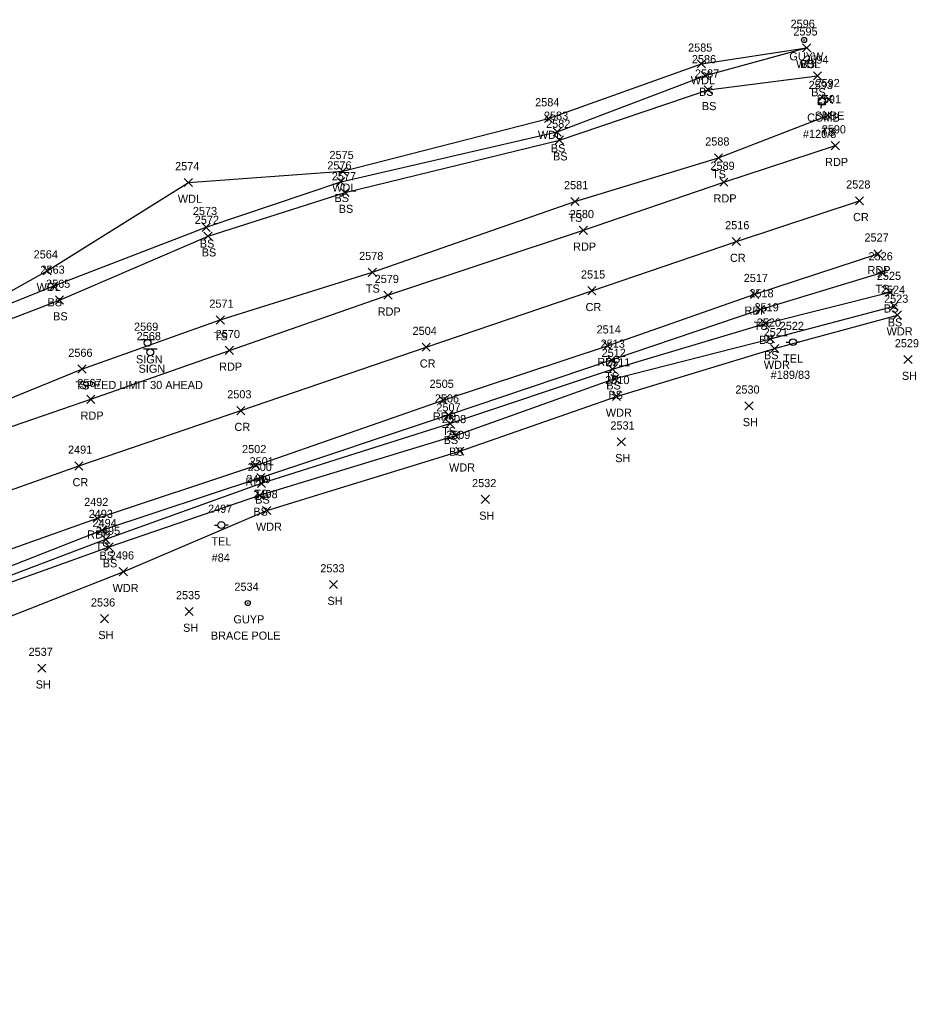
# Model space of a CAD drawing. Extents: x 1699408 to 1700423, y 840176 to 841410.
# Drawn here: x 1700202.3 to 1700423, y 840318.6 to 840558.1 of the extents above; entities that cross this region are included whole.
import ezdxf

# ---------------------------------------------------------------- set-up
doc = ezdxf.new("R2010")
doc.units = 0
for name, color, linetype in [('L_A', 7, 'Continuous'), ('L_I', 7, 'Continuous'), ('L_TIC', 7, 'Continuous'), ('LAWA', 7, 'Continuous'), ('LELB', 7, 'Continuous'), ('P_A', 7, 'Continuous'), ('P_I', 7, 'Continuous'), ('P_TIC', 7, 'Continuous'), ('PET', 7, 'Continuous'), ('PRC', 7, 'Continuous'), ('S_A', 7, 'Continuous'), ('S_C', 7, 'Continuous'), ('S_I', 7, 'Continuous'), ('SSGN', 7, 'Continuous'), ('U_A', 7, 'Continuous'), ('U_C', 7, 'Continuous'), ('U_I', 7, 'Continuous'), ('U_TIC', 7, 'Continuous'), ('UP', 7, 'Continuous'), ('UPGW', 7, 'Continuous')]:
    doc.layers.add(name, color=color, linetype=linetype)

msp = doc.modelspace()

# ---------------------------------------------------------------- linework, layer by layer
at = {"layer": 'L_TIC'}
for points in [[(1700394.55, 840550.16), (1700396.55, 840552.16)], [(1700396.55, 840550.16), (1700394.55, 840552.16)], [(1700394.55, 840550.16), (1700396.55, 840552.16)], [(1700396.55, 840550.16), (1700394.55, 840552.16)], [(1700368.71, 840546.2), (1700370.71, 840548.2)], [(1700370.71, 840546.2), (1700368.71, 840548.2)], [(1700369.69, 840543.36), (1700371.69, 840545.36)], [(1700371.69, 840543.36), (1700369.69, 840545.36)], [(1700397.24, 840543.25), (1700399.24, 840545.25)], [(1700399.24, 840543.25), (1700397.24, 840545.25)], [(1700370.4, 840539.85), (1700372.4, 840541.85)], [(1700372.4, 840539.85), (1700370.4, 840541.85)], [(1700331.18, 840532.79), (1700333.18, 840534.79)], [(1700333.18, 840532.79), (1700331.18, 840534.79)], [(1700399.76, 840533.56), (1700401.76, 840535.56)], [(1700401.76, 840533.56), (1700399.76, 840535.56)], [(1700333.33, 840529.5), (1700335.33, 840531.5)], [(1700335.33, 840529.5), (1700333.33, 840531.5)], [(1700333.86, 840527.51), (1700335.86, 840529.51)], [(1700335.86, 840527.51), (1700333.86, 840529.51)], [(1700372.92, 840523.16), (1700374.92, 840525.16)], [(1700374.92, 840523.16), (1700372.92, 840525.16)], [(1700280.69, 840519.84), (1700282.69, 840521.84)], [(1700282.69, 840519.84), (1700280.69, 840521.84)], [(1700242.79, 840517.11), (1700244.79, 840519.11)], [(1700244.79, 840517.11), (1700242.79, 840519.11)], [(1700280.22, 840517.3), (1700282.22, 840519.3)], [(1700282.22, 840517.3), (1700280.22, 840519.3)], [(1700281.26, 840514.64), (1700283.26, 840516.64)], [(1700283.26, 840514.64), (1700281.26, 840516.64)], [(1700337.68, 840512.45), (1700339.68, 840514.45)], [(1700339.68, 840512.45), (1700337.68, 840514.45)], [(1700247.16, 840506.11), (1700249.16, 840508.11)], [(1700249.16, 840506.11), (1700247.16, 840508.11)], [(1700247.63, 840503.95), (1700249.63, 840505.95)], [(1700249.63, 840503.95), (1700247.63, 840505.95)], [(1700208.13, 840495.46), (1700210.13, 840497.46)], [(1700210.13, 840495.46), (1700208.13, 840497.46)], [(1700287.96, 840495.07), (1700289.96, 840497.07)], [(1700289.96, 840495.07), (1700287.96, 840497.07)], [(1700413.06, 840494.99), (1700415.06, 840496.99)], [(1700415.06, 840494.99), (1700413.06, 840496.99)], [(1700209.79, 840491.71), (1700211.79, 840493.71)], [(1700211.79, 840491.71), (1700209.79, 840493.71)], [(1700415.04, 840490.19), (1700417.04, 840492.19)], [(1700417.04, 840490.19), (1700415.04, 840492.19)], [(1700211.16, 840488.26), (1700213.16, 840490.26)], [(1700213.16, 840488.26), (1700211.16, 840490.26)], [(1700416.03, 840486.78), (1700418.03, 840488.78)], [(1700418.03, 840486.78), (1700416.03, 840488.78)], [(1700383.18, 840485.92), (1700385.18, 840487.92)], [(1700385.18, 840485.92), (1700383.18, 840487.92)], [(1700416.82, 840484.58), (1700418.82, 840486.58)], [(1700418.82, 840484.58), (1700416.82, 840486.58)], [(1700250.63, 840483.37), (1700252.63, 840485.37)], [(1700252.63, 840483.37), (1700250.63, 840485.37)], [(1700384.46, 840482.48), (1700386.46, 840484.48)], [(1700386.46, 840482.48), (1700384.46, 840484.48)], [(1700385.66, 840478.73), (1700387.66, 840480.73)], [(1700387.66, 840478.73), (1700385.66, 840480.73)], [(1700386.69, 840476.37), (1700388.69, 840478.37)], [(1700388.69, 840476.37), (1700386.69, 840478.37)], [(1700346.68, 840473.56), (1700348.68, 840475.56)], [(1700348.68, 840473.56), (1700346.68, 840475.56)], [(1700419.45, 840473.66), (1700421.45, 840475.66)], [(1700421.45, 840473.66), (1700419.45, 840475.66)], [(1700216.68, 840471.32), (1700218.68, 840473.32)], [(1700218.68, 840471.32), (1700216.68, 840473.32)], [(1700346.92, 840471.31), (1700348.92, 840473.31)], [(1700348.92, 840471.31), (1700346.92, 840473.31)], [(1700347.46, 840468.98), (1700349.46, 840470.98)], [(1700349.46, 840468.98), (1700347.46, 840470.98)], [(1700347.89, 840464.62), (1700349.89, 840466.62)], [(1700349.89, 840464.62), (1700347.89, 840466.62)], [(1700380.4, 840462.3), (1700382.4, 840464.3)], [(1700382.4, 840462.3), (1700380.4, 840464.3)], [(1700306.68, 840460.11), (1700308.68, 840462.11)], [(1700308.68, 840460.11), (1700306.68, 840462.11)], [(1700307.01, 840457.93), (1700309.01, 840459.93)], [(1700309.01, 840457.93), (1700307.01, 840459.93)], [(1700308.36, 840455.05), (1700310.36, 840457.05)], [(1700310.36, 840455.05), (1700308.36, 840457.05)], [(1700349.08, 840453.48), (1700351.08, 840455.48)], [(1700351.08, 840453.48), (1700349.08, 840455.48)], [(1700309.41, 840451.18), (1700311.41, 840453.18)], [(1700311.41, 840451.18), (1700309.41, 840453.18)], [(1700260.59, 840444.7), (1700262.59, 840446.7)], [(1700262.59, 840444.7), (1700260.59, 840446.7)], [(1700260.76, 840443.29), (1700262.76, 840445.29)], [(1700262.76, 840443.29), (1700260.76, 840445.29)], [(1700260.3, 840440.34), (1700262.3, 840442.34)], [(1700262.3, 840440.34), (1700260.3, 840442.34)], [(1700315.7, 840439.35), (1700317.7, 840441.35)], [(1700317.7, 840439.35), (1700315.7, 840441.35)], [(1700262.02, 840436.63), (1700264.02, 840438.63)], [(1700264.02, 840436.63), (1700262.02, 840438.63)], [(1700221.58, 840431.8), (1700223.58, 840433.8)], [(1700223.58, 840431.8), (1700221.58, 840433.8)], [(1700222.53, 840429.55), (1700224.53, 840431.55)], [(1700224.53, 840429.55), (1700222.53, 840431.55)], [(1700223.35, 840427.66), (1700225.35, 840429.66)], [(1700225.35, 840427.66), (1700223.35, 840429.66)], [(1700226.82, 840421.6), (1700228.82, 840423.6)], [(1700228.82, 840421.6), (1700226.82, 840423.6)], [(1700278.44, 840418.44), (1700280.44, 840420.44)], [(1700280.44, 840418.44), (1700278.44, 840420.44)], [(1700222.2, 840410.06), (1700224.2, 840412.06)], [(1700224.2, 840410.06), (1700222.2, 840412.06)], [(1700243.01, 840411.85), (1700245.01, 840413.85)], [(1700245.01, 840411.85), (1700243.01, 840413.85)], [(1700206.83, 840397.94), (1700208.83, 840399.94)], [(1700208.83, 840397.94), (1700206.83, 840399.94)]]:
    msp.add_lwpolyline(points, dxfattribs=at)
at = {"layer": 'LAWA'}
for points in [[(1700145.03, 840478.23), (1700165.1, 840473.44), (1700178.86, 840476.43), (1700181.12, 840480.8), (1700209.13, 840496.46), (1700243.79, 840518.11), (1700281.69, 840520.84), (1700332.18, 840533.79), (1700369.71, 840547.2), (1700395.55, 840551.16)], [(1700117.89, 840346.79), (1700115.47, 840370.34), (1700134.74, 840381.65), (1700175.24, 840399.81), (1700196.37, 840410.18), (1700227.82, 840422.6), (1700263.02, 840437.63), (1700310.41, 840452.18), (1700348.89, 840465.62), (1700387.69, 840477.37), (1700417.82, 840485.58)]]:
    msp.add_lwpolyline(points, dxfattribs=at)
at = {"layer": 'LELB'}
for points in [[(1700181.12, 840480.8), (1700210.79, 840492.71), (1700248.16, 840507.11), (1700281.22, 840518.3), (1700334.33, 840530.5), (1700370.69, 840544.36), (1700395.55, 840551.16)], [(1700178.86, 840476.43), (1700212.16, 840489.26), (1700248.63, 840504.95), (1700282.26, 840515.64), (1700334.86, 840528.51), (1700371.4, 840540.85), (1700398.24, 840544.25)], [(1700136.81, 840473.48), (1700138.8, 840459.12), (1700153.66, 840446.5), (1700160.98, 840449.17), (1700182.9, 840458.15), (1700217.68, 840472.32), (1700251.63, 840484.37), (1700288.96, 840496.07), (1700338.68, 840513.45), (1700373.92, 840524.16), (1700400.76, 840534.56)], [(1699894.91, 840318.62), (1699909.54, 840320.37), (1699931.73, 840326.89), (1699942.77, 840330.34), (1699953.04, 840332.24), (1699965.49, 840337.33), (1699971.91, 840344.73), (1700003.63, 840352.88), (1700032.87, 840363), (1700063.25, 840372.76), (1700109.93, 840390.42), (1700140.91, 840399), (1700170.04, 840412.16), (1700222.58, 840432.8), (1700261.59, 840445.7), (1700307.68, 840461.11), (1700347.68, 840474.56), (1700384.18, 840486.92), (1700414.06, 840495.99)], [(1699950.19, 840322.46), (1699970.52, 840330.95), (1699975.9, 840338.67), (1700003.21, 840345.94), (1700034.35, 840356.49), (1700066.22, 840366.04), (1700111.96, 840382.71), (1700172.64, 840406.47), (1700188.14, 840417.18), (1700223.53, 840430.55), (1700261.76, 840444.29), (1700308.01, 840458.93), (1700347.92, 840472.31), (1700385.46, 840483.48), (1700416.04, 840491.19)], [(1700177.27, 840387.2), (1700175.24, 840399.81), (1700188.97, 840416.03), (1700224.35, 840428.66), (1700261.3, 840441.34), (1700309.36, 840456.05), (1700348.46, 840469.98), (1700386.66, 840479.73), (1700417.03, 840487.78)]]:
    msp.add_lwpolyline(points, dxfattribs=at)
at = {"layer": 'P_TIC'}
for points in [[(1700401.6, 840526.14), (1700403.6, 840528.14)], [(1700403.6, 840526.14), (1700401.6, 840528.14)], [(1700374.21, 840517.2), (1700376.21, 840519.2)], [(1700376.21, 840517.2), (1700374.21, 840519.2)], [(1700407.52, 840512.62), (1700409.52, 840514.62)], [(1700409.52, 840512.62), (1700407.52, 840514.62)], [(1700339.75, 840505.36), (1700341.75, 840507.36)], [(1700341.75, 840505.36), (1700339.75, 840507.36)], [(1700377.3, 840502.62), (1700379.3, 840504.62)], [(1700379.3, 840502.62), (1700377.3, 840504.62)], [(1700412.01, 840499.61), (1700414.01, 840501.61)], [(1700414.01, 840499.61), (1700412.01, 840501.61)], [(1700291.78, 840489.43), (1700293.78, 840491.43)], [(1700293.78, 840489.43), (1700291.78, 840491.43)], [(1700341.85, 840490.54), (1700343.85, 840492.54)], [(1700343.85, 840490.54), (1700341.85, 840492.54)], [(1700381.8, 840489.67), (1700383.8, 840491.67)], [(1700383.8, 840489.67), (1700381.8, 840491.67)], [(1700345.69, 840477.05), (1700347.69, 840479.05)], [(1700347.69, 840477.05), (1700345.69, 840479.05)], [(1700252.86, 840475.91), (1700254.86, 840477.91)], [(1700254.86, 840475.91), (1700252.86, 840477.91)], [(1700301.17, 840476.7), (1700303.17, 840478.7)], [(1700303.17, 840476.7), (1700301.17, 840478.7)], [(1700218.84, 840463.9), (1700220.84, 840465.9)], [(1700220.84, 840463.9), (1700218.84, 840465.9)], [(1700305.34, 840463.7), (1700307.34, 840465.7)], [(1700307.34, 840463.7), (1700305.34, 840465.7)], [(1700255.68, 840461.13), (1700257.68, 840463.13)], [(1700257.68, 840461.13), (1700255.68, 840463.13)], [(1700215.93, 840447.55), (1700217.93, 840449.55)], [(1700217.93, 840447.55), (1700215.93, 840449.55)], [(1700259.32, 840447.69), (1700261.32, 840449.69)], [(1700261.32, 840447.69), (1700259.32, 840449.69)], [(1700220.46, 840434.72), (1700222.46, 840436.72)], [(1700222.46, 840434.72), (1700220.46, 840436.72)]]:
    msp.add_lwpolyline(points, dxfattribs=at)
at = {"layer": 'PET'}
for points in [[(1700021.62, 840396.71), (1700043.81, 840403.93), (1700089.04, 840420.89), (1700114.15, 840429.08), (1700156, 840442.24), (1700184.2, 840452.68), (1700219.84, 840464.9), (1700253.86, 840476.91), (1700292.78, 840490.43), (1700340.75, 840506.36), (1700375.21, 840518.2), (1700402.6, 840527.14)], [(1700000.7, 840359.42), (1700031.35, 840369.03), (1700061.33, 840378.61), (1700109.24, 840395.28), (1700138.79, 840406.02), (1700172.93, 840418.49), (1700221.46, 840435.72), (1700260.32, 840448.69), (1700306.34, 840464.7), (1700346.69, 840478.05), (1700382.8, 840490.67), (1700413.01, 840500.61)]]:
    msp.add_lwpolyline(points, dxfattribs=at)
at = {"layer": 'PRC'}
msp.add_lwpolyline([(1699996.81, 840372.51), (1700026.94, 840382.38), (1700056.52, 840392.21), (1700105.22, 840409.05), (1700134.27, 840419.13), (1700168.35, 840431.32), (1700216.93, 840448.55), (1700256.68, 840462.13), (1700302.17, 840477.7), (1700342.85, 840491.54), (1700378.3, 840503.62), (1700408.52, 840513.62)], dxfattribs=at)
at = {"layer": 'SSGN'}
for p, q in [((1700232.14, 840479.57), (1700235.48, 840479.57)), ((1700232.78, 840477.27), (1700236.12, 840477.27)), ((1700233.79, 840478.74), (1700233.79, 840478.74)), ((1700234.43, 840476.43), (1700234.43, 840476.43))]:
    msp.add_line(p, q, dxfattribs=at)
for centre in [(1700233.79, 840478.74), (1700234.43, 840476.43)]:
    msp.add_circle(centre, 0.833, dxfattribs=at)
at = {"layer": 'U_TIC'}
for points in [[(1700399.99, 840537.5), (1700401.99, 840539.5)], [(1700401.99, 840537.5), (1700399.99, 840539.5)]]:
    msp.add_lwpolyline(points, dxfattribs=at)
at = {"layer": 'UP'}
for p, q in [((1700398.47, 840537.19), (1700398.47, 840538.86)), ((1700398.47, 840538.86), (1700400.13, 840538.86)), ((1700399.55, 840539.69), (1700399.3, 840538.86)), ((1700400.13, 840538.86), (1700400.13, 840537.19)), ((1700400.13, 840537.19), (1700398.47, 840537.19)), ((1700399.05, 840536.36), (1700399.3, 840537.19)), ((1700399.3, 840538.03), (1700399.3, 840538.03)), ((1700390.54, 840478.9), (1700391.37, 840478.9)), ((1700392.2, 840478.91), (1700392.2, 840478.91)), ((1700393.87, 840478.91), (1700393.04, 840478.91)), ((1700393.04, 840478.91), (1700393.04, 840478.91)), ((1700393.87, 840478.91), (1700393.87, 840478.91)), ((1700250.22, 840434.05), (1700251.05, 840434.05)), ((1700251.88, 840434.05), (1700251.88, 840434.05)), ((1700253.55, 840434.05), (1700252.71, 840434.05)), ((1700252.71, 840434.05), (1700252.71, 840434.05)), ((1700253.55, 840434.05), (1700253.55, 840434.05))]:
    msp.add_line(p, q, dxfattribs=at)
for centre in [(1700399.3, 840538.03), (1700392.2, 840478.91), (1700251.88, 840434.05)]:
    msp.add_circle(centre, 0.833, dxfattribs=at)
at = {"layer": 'UPGW'}
for centre, radius in [((1700394.93, 840553.06), 0.625), ((1700394.93, 840553.06), 0.0833), ((1700258.36, 840414.91), 0.625), ((1700258.36, 840414.91), 0.0833)]:
    msp.add_circle(centre, radius, dxfattribs=at)

# ---------------------------------------------------------------- texts
at = {"layer": 'L_A'}
for s, p in [('WDL', (1700392.97, 840546.16)), ('BS', (1700393.99, 840546.16)), ('WDL', (1700367.12, 840542.2)), ('BS', (1700369.13, 840539.36)), ('BS', (1700396.68, 840539.25)), ('BS', (1700369.84, 840535.85)), ('WDL', (1700329.59, 840528.79)), ('TS', (1700399.16, 840529.56)), ('BS', (1700332.77, 840525.5)), ('BS', (1700333.3, 840523.51)), ('TS', (1700372.33, 840519.16)), ('WDL', (1700279.1, 840515.84)), ('WDL', (1700241.21, 840513.11)), ('BS', (1700279.66, 840513.3)), ('BS', (1700280.7, 840510.64)), ('TS', (1700337.09, 840508.45)), ('BS', (1700246.6, 840502.11)), ('BS', (1700247.07, 840499.95)), ('WDL', (1700206.55, 840491.46)), ('TS', (1700287.37, 840491.07)), ('TS', (1700412.47, 840490.99)), ('BS', (1700209.23, 840487.71)), ('BS', (1700210.6, 840484.26)), ('BS', (1700414.48, 840486.19)), ('TS', (1700382.59, 840481.92)), ('BS', (1700415.47, 840482.78)), ('TS', (1700250.04, 840479.37)), ('WDR', (1700415.19, 840480.58)), ('BS', (1700383.9, 840478.48)), ('BS', (1700385.1, 840474.73)), ('WDR', (1700385.05, 840472.37)), ('TS', (1700346.09, 840469.56)), ('SH', (1700418.94, 840469.66)), ('TS', (1700216.09, 840467.32)), ('BS', (1700346.37, 840467.31)), ('BS', (1700346.9, 840464.98)), ('WDR', (1700346.26, 840460.62)), ('SH', (1700379.89, 840458.3)), ('TS', (1700306.09, 840456.11)), ('BS', (1700306.45, 840453.93)), ('BS', (1700307.8, 840451.05)), ('SH', (1700348.57, 840449.48)), ('WDR', (1700307.77, 840447.18)), ('TS', (1700260, 840440.7)), ('BS', (1700260.2, 840439.29)), ('BS', (1700259.74, 840436.34)), ('SH', (1700315.19, 840435.35)), ('WDR', (1700260.38, 840432.63)), ('TS', (1700220.98, 840427.8)), ('BS', (1700221.97, 840425.55)), ('BS', (1700222.79, 840423.66)), ('WDR', (1700225.19, 840417.6)), ('SH', (1700277.93, 840414.44)), ('SH', (1700242.5, 840407.85)), ('SH', (1700221.69, 840406.06)), ('SH', (1700206.31, 840393.94))]:
    msp.add_text(s, height=2, dxfattribs=at).set_placement(p)
at = {"layer": 'L_I'}
for s, p in [('2595', (1700392.29, 840554.16)), ('2595', (1700392.29, 840554.16)), ('2585', (1700366.45, 840550.2)), ('2586', (1700367.38, 840547.36)), ('2594', (1700394.98, 840547.25)), ('2587', (1700368.14, 840543.85)), ('2591', (1700398.06, 840537.56)), ('2584', (1700328.92, 840536.79)), ('2583', (1700331.07, 840533.5)), ('2582', (1700331.6, 840531.51)), ('2588', (1700370.66, 840527.16)), ('2575', (1700278.43, 840523.84)), ('2574', (1700240.54, 840521.11)), ('2576', (1700277.9, 840521.3)), ('2577', (1700279, 840518.64)), ('2581', (1700335.99, 840516.45)), ('2573', (1700244.9, 840510.11)), ('2572', (1700245.37, 840507.95)), ('2564', (1700205.82, 840499.46)), ('2578', (1700285.7, 840499.07)), ('2526', (1700410.74, 840498.99)), ('2563', (1700207.49, 840495.71)), ('2525', (1700412.78, 840494.19)), ('2565', (1700208.86, 840492.26)), ('2518', (1700381.49, 840489.92)), ('2524', (1700413.77, 840490.78)), ('2571', (1700248.94, 840487.37)), ('2523', (1700414.56, 840488.58)), ('2519', (1700382.76, 840486.48)), ('2520', (1700383.31, 840482.73)), ('2521', (1700385, 840480.37)), ('2513', (1700344.99, 840477.56)), ('2529', (1700417.19, 840477.66)), ('2566', (1700214.32, 840475.32)), ('2512', (1700345.23, 840475.31)), ('2511', (1700346.33, 840472.98)), ('2510', (1700346.11, 840468.62)), ('2530', (1700378.06, 840466.3)), ('2506', (1700304.28, 840464.11)), ('2507', (1700304.67, 840461.93)), ('2508', (1700306.02, 840459.05)), ('2531', (1700347.39, 840457.48)), ('2509', (1700307.06, 840455.18)), ('2501', (1700258.82, 840448.7)), ('2500', (1700258.34, 840447.29)), ('2499', (1700258.03, 840444.34)), ('2532', (1700313.44, 840443.35)), ('2498', (1700259.76, 840440.63)), ('2493', (1700219.32, 840435.8)), ('2494', (1700220.27, 840433.55)), ('2495', (1700221.09, 840431.66)), ('2496', (1700224.51, 840425.6)), ('2533', (1700276.18, 840422.44)), ('2535', (1700240.75, 840415.85)), ('2536', (1700219.88, 840414.06)), ('2537', (1700204.57, 840401.94))]:
    msp.add_text(s, height=2, dxfattribs=at).set_placement(p)
at = {"layer": 'P_A'}
for s, p in [('RDP', (1700400.09, 840522.14)), ('RDP', (1700372.7, 840513.2)), ('CR', (1700406.95, 840508.62)), ('RDP', (1700338.24, 840501.36)), ('CR', (1700376.73, 840498.62)), ('RDP', (1700410.5, 840495.61)), ('CR', (1700341.28, 840486.54)), ('RDP', (1700290.27, 840485.43)), ('RDP', (1700380.29, 840485.67)), ('CR', (1700300.6, 840472.7)), ('RDP', (1700344.18, 840473.05)), ('RDP', (1700251.35, 840471.91)), ('RDP', (1700217.33, 840459.9)), ('RDP', (1700303.82, 840459.7)), ('CR', (1700255.11, 840457.13)), ('CR', (1700215.37, 840443.55)), ('RDP', (1700257.81, 840443.69)), ('RDP', (1700218.95, 840430.72))]:
    msp.add_text(s, height=2, dxfattribs=at).set_placement(p)
at = {"layer": 'P_I'}
for s, p in [('2590', (1700399.25, 840530.14)), ('2589', (1700371.94, 840521.2)), ('2528', (1700405.26, 840516.62)), ('2580', (1700337.4, 840509.36)), ('2516', (1700375.55, 840506.62)), ('2527', (1700409.75, 840503.61)), ('2515', (1700340.16, 840494.54)), ('2579', (1700289.52, 840493.43)), ('2517', (1700380.11, 840493.67)), ('2570', (1700250.51, 840479.91)), ('2504', (1700298.83, 840480.7)), ('2514', (1700344, 840481.05)), ('2567', (1700216.54, 840467.9)), ('2505', (1700303, 840467.7)), ('2503', (1700253.34, 840465.13)), ('2491', (1700214.24, 840451.55)), ('2502', (1700256.98, 840451.69)), ('2492', (1700218.2, 840438.72))]:
    msp.add_text(s, height=2, dxfattribs=at).set_placement(p)
at = {"layer": 'S_A'}
for p in [(1700230.93, 840473.72), (1700231.57, 840471.41)]:
    msp.add_text('SIGN', height=2, dxfattribs=at).set_placement(p)
at = {"layer": 'S_C'}
msp.add_text('SPEED LIMIT 30 AHEAD', height=2, dxfattribs=at).set_placement((1700217.03, 840467.41))
at = {"layer": 'S_I'}
for s, p in [('2569', (1700230.46, 840481.72)), ('2568', (1700231.1, 840479.41))]:
    msp.add_text(s, height=2, dxfattribs=at).set_placement(p)
at = {"layer": 'U_A'}
for s, p in [('GUYW', (1700391.32, 840548.06)), ('COMB', (1700395.68, 840533.03)), ('SUBE', (1700397.53, 840533.5)), ('TEL', (1700389.76, 840473.91)), ('TEL', (1700249.44, 840429.05)), ('GUYP', (1700254.87, 840409.91))]:
    msp.add_text(s, height=2, dxfattribs=at).set_placement(p)
at = {"layer": 'U_C'}
for s, p in [('#120/8', (1700394.65, 840529.03)), ('#189/83', (1700386.74, 840469.91)), ('#84', (1700249.52, 840425.05)), ('BRACE POLE', (1700249.32, 840405.91))]:
    msp.add_text(s, height=2, dxfattribs=at).set_placement(p)
at = {"layer": 'U_I'}
for s, p in [('2596', (1700391.61, 840556.06)), ('2593', (1700396.04, 840541.03)), ('2592', (1700397.73, 840541.5)), ('2522', (1700388.94, 840481.91)), ('2497', (1700248.62, 840437.05)), ('2534', (1700255.1, 840417.91))]:
    msp.add_text(s, height=2, dxfattribs=at).set_placement(p)

doc.saveas('drawing.dxf')
